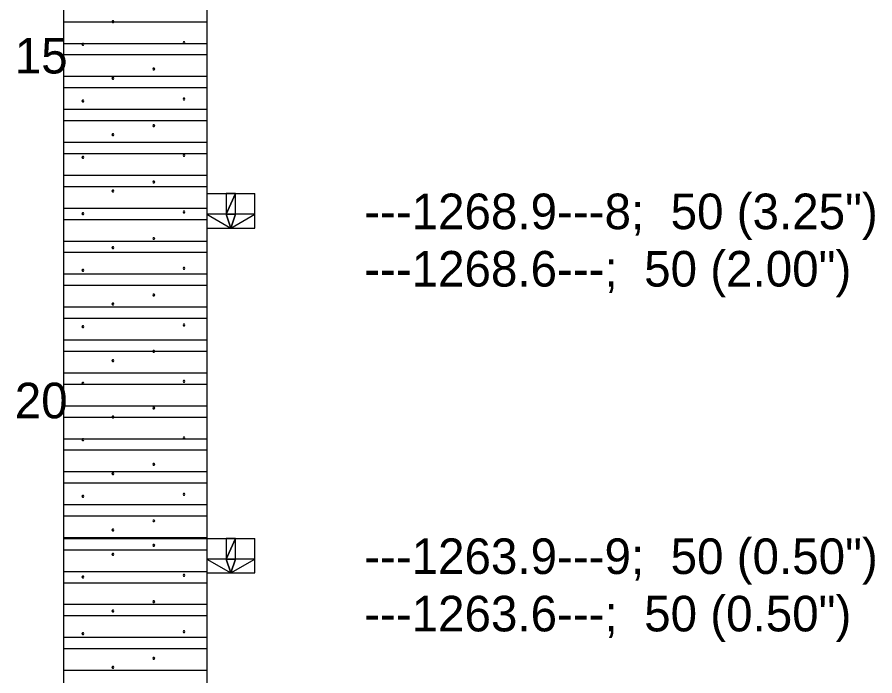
# Model space of a CAD drawing. Extents: x 2150148.6 to 2150220.1, y 143803.7 to 143875.1.
# Drawn here: x 2150191.798 to 2150194.79, y 143822.25 to 143824.546 of the extents above; entities that cross this region are included whole.
import ezdxf

# ---------------------------------------------------------------- set-up
doc = ezdxf.new("R2010")
doc.units = 0
doc.layers.add('Default', color=7, linetype='Continuous')

msp = doc.modelspace()

# ---------------------------------------------------------------- linework, layer by layer
at = {"layer": 'Default'}
for points in [[(2150191.9604, 143828.0174), (2150191.9604, 143817.9213)], [(2150192.4604, 143828.0174), (2150192.4604, 143817.9213)], [(2150191.9604, 143824.53), (2150192.4604, 143824.53)], [(2150192.1355, 143824.5299), (2150192.1338, 143824.5328), (2150192.1306, 143824.5328), (2150192.1289, 143824.53), (2150192.1306, 143824.5271), (2150192.1338, 143824.5271), (2150192.1355, 143824.5299)], [(2150192.3836, 143824.4575), (2150192.3819, 143824.4604), (2150192.3787, 143824.4604), (2150192.377, 143824.4575), (2150192.3787, 143824.4547), (2150192.3819, 143824.4547), (2150192.3836, 143824.4575)], [(2150191.9604, 143824.4545), (2150192.4604, 143824.4545)], [(2150192.0308, 143824.451), (2150192.0292, 143824.4538), (2150192.0259, 143824.4538), (2150192.0243, 143824.451), (2150192.0259, 143824.4481), (2150192.0292, 143824.4481), (2150192.0308, 143824.451)], [(2150191.9604, 143824.4152), (2150192.4604, 143824.4152)], [(2150192.2781, 143824.365), (2150192.2764, 143824.3678), (2150192.2731, 143824.3678), (2150192.2715, 143824.365), (2150192.2731, 143824.3622), (2150192.2764, 143824.3622), (2150192.2781, 143824.365)], [(2150191.9604, 143824.3397), (2150192.4604, 143824.3397)], [(2150192.1355, 143824.3331), (2150192.1338, 143824.336), (2150192.1306, 143824.336), (2150192.1289, 143824.3331), (2150192.1306, 143824.3303), (2150192.1338, 143824.3303), (2150192.1355, 143824.3331)], [(2150191.9604, 143824.3003), (2150192.4604, 143824.3003)], [(2150192.0308, 143824.2541), (2150192.0292, 143824.257), (2150192.0259, 143824.257), (2150192.0243, 143824.2541), (2150192.0259, 143824.2513), (2150192.0292, 143824.2513), (2150192.0308, 143824.2541)], [(2150192.3836, 143824.2606), (2150192.3819, 143824.2635), (2150192.3787, 143824.2635), (2150192.377, 143824.2606), (2150192.3787, 143824.2578), (2150192.3819, 143824.2578), (2150192.3836, 143824.2606)], [(2150191.9604, 143824.2249), (2150192.4604, 143824.2249)], [(2150191.9604, 143824.1855), (2150192.4604, 143824.1855)], [(2150192.2781, 143824.1681), (2150192.2764, 143824.1709), (2150192.2731, 143824.1709), (2150192.2715, 143824.1681), (2150192.2731, 143824.1653), (2150192.2764, 143824.1653), (2150192.2781, 143824.1681)], [(2150192.1355, 143824.1362), (2150192.1338, 143824.1391), (2150192.1306, 143824.1391), (2150192.1289, 143824.1363), (2150192.1306, 143824.1334), (2150192.1338, 143824.1334), (2150192.1355, 143824.1362)], [(2150191.9604, 143824.1101), (2150192.4604, 143824.1101)], [(2150191.9604, 143824.0707), (2150192.4604, 143824.0707)], [(2150192.0308, 143824.0573), (2150192.0292, 143824.0601), (2150192.0259, 143824.0601), (2150192.0243, 143824.0573), (2150192.0259, 143824.0544), (2150192.0292, 143824.0544), (2150192.0308, 143824.0573)], [(2150192.3836, 143824.0638), (2150192.3819, 143824.0667), (2150192.3787, 143824.0667), (2150192.377, 143824.0638), (2150192.3787, 143824.061), (2150192.3819, 143824.061), (2150192.3836, 143824.0638)], [(2150191.9604, 143823.9952), (2150192.4604, 143823.9952)], [(2150191.9604, 143823.9559), (2150192.4604, 143823.9559)], [(2150192.2781, 143823.9713), (2150192.2764, 143823.9741), (2150192.2731, 143823.9741), (2150192.2715, 143823.9713), (2150192.2731, 143823.9685), (2150192.2764, 143823.9685), (2150192.2781, 143823.9713)], [(2150192.1355, 143823.9394), (2150192.1338, 143823.9423), (2150192.1306, 143823.9423), (2150192.1289, 143823.9394), (2150192.1306, 143823.9366), (2150192.1338, 143823.9366), (2150192.1355, 143823.9394)], [(2150192.4604, 143823.9309), (2150192.6271, 143823.9309)], [(2150192.6271, 143823.8107), (2150192.6271, 143823.9309)], [(2150191.9604, 143823.8804), (2150192.4604, 143823.8804)], [(2150192.0308, 143823.8604), (2150192.0292, 143823.8633), (2150192.0259, 143823.8633), (2150192.0243, 143823.8604), (2150192.0259, 143823.8576), (2150192.0292, 143823.8576), (2150192.0308, 143823.8604)], [(2150192.3836, 143823.8669), (2150192.3819, 143823.8698), (2150192.3787, 143823.8698), (2150192.377, 143823.8669), (2150192.3787, 143823.8641), (2150192.3819, 143823.8641), (2150192.3836, 143823.8669)], [(2150191.9604, 143823.841), (2150192.4604, 143823.841)], [(2150192.4604, 143823.8107), (2150192.6271, 143823.8107)], [(2150192.2781, 143823.7744), (2150192.2764, 143823.7772), (2150192.2731, 143823.7772), (2150192.2715, 143823.7744), (2150192.2731, 143823.7716), (2150192.2764, 143823.7716), (2150192.2781, 143823.7744)], [(2150191.9604, 143823.7656), (2150192.4604, 143823.7656)], [(2150192.1355, 143823.7425), (2150192.1338, 143823.7454), (2150192.1306, 143823.7454), (2150192.1289, 143823.7426), (2150192.1306, 143823.7397), (2150192.1338, 143823.7397), (2150192.1355, 143823.7425)], [(2150191.9604, 143823.7262), (2150192.4604, 143823.7262)], [(2150191.9604, 143823.6507), (2150192.4604, 143823.6507)], [(2150192.0308, 143823.6636), (2150192.0292, 143823.6664), (2150192.0259, 143823.6664), (2150192.0243, 143823.6636), (2150192.0259, 143823.6607), (2150192.0292, 143823.6607), (2150192.0308, 143823.6636)], [(2150192.3836, 143823.6701), (2150192.3819, 143823.673), (2150192.3787, 143823.673), (2150192.377, 143823.6701), (2150192.3787, 143823.6673), (2150192.3819, 143823.6673), (2150192.3836, 143823.6701)], [(2150191.9604, 143823.6114), (2150192.4604, 143823.6114)], [(2150192.2781, 143823.5776), (2150192.2764, 143823.5804), (2150192.2731, 143823.5804), (2150192.2715, 143823.5776), (2150192.2731, 143823.5748), (2150192.2764, 143823.5748), (2150192.2781, 143823.5776)], [(2150191.9604, 143823.5359), (2150192.4604, 143823.5359)], [(2150192.1355, 143823.5457), (2150192.1338, 143823.5486), (2150192.1306, 143823.5486), (2150192.1289, 143823.5457), (2150192.1306, 143823.5429), (2150192.1338, 143823.5429), (2150192.1355, 143823.5457)], [(2150191.9604, 143823.4965), (2150192.4604, 143823.4965)], [(2150192.0308, 143823.4667), (2150192.0292, 143823.4696), (2150192.0259, 143823.4696), (2150192.0243, 143823.4667), (2150192.0259, 143823.4639), (2150192.0292, 143823.4639), (2150192.0308, 143823.4667)], [(2150192.3836, 143823.4732), (2150192.3819, 143823.4761), (2150192.3787, 143823.4761), (2150192.377, 143823.4732), (2150192.3787, 143823.4704), (2150192.3819, 143823.4704), (2150192.3836, 143823.4732)], [(2150191.9604, 143823.4211), (2150192.4604, 143823.4211)], [(2150191.9604, 143823.3817), (2150192.4604, 143823.3817)], [(2150192.2781, 143823.3807), (2150192.2764, 143823.3835), (2150192.2731, 143823.3835), (2150192.2715, 143823.3807), (2150192.2731, 143823.3779), (2150192.2764, 143823.3779), (2150192.2781, 143823.3807)], [(2150192.1355, 143823.3488), (2150192.1338, 143823.3517), (2150192.1306, 143823.3517), (2150192.1289, 143823.3489), (2150192.1306, 143823.346), (2150192.1338, 143823.346), (2150192.1355, 143823.3488)], [(2150191.9604, 143823.3062), (2150192.4604, 143823.3062)], [(2150191.9604, 143823.2669), (2150192.4604, 143823.2669)], [(2150192.0308, 143823.2699), (2150192.0292, 143823.2727), (2150192.0259, 143823.2727), (2150192.0243, 143823.2699), (2150192.0259, 143823.267), (2150192.0292, 143823.267), (2150192.0308, 143823.2699)], [(2150192.3836, 143823.2764), (2150192.3819, 143823.2793), (2150192.3787, 143823.2793), (2150192.377, 143823.2764), (2150192.3787, 143823.2736), (2150192.3819, 143823.2736), (2150192.3836, 143823.2764)], [(2150191.9604, 143823.1914), (2150192.4604, 143823.1914)], [(2150192.2781, 143823.1839), (2150192.2764, 143823.1867), (2150192.2731, 143823.1867), (2150192.2715, 143823.1839), (2150192.2731, 143823.1811), (2150192.2764, 143823.1811), (2150192.2781, 143823.1839)], [(2150191.9604, 143823.152), (2150192.4604, 143823.152)], [(2150192.1355, 143823.152), (2150192.1338, 143823.1549), (2150192.1306, 143823.1549), (2150192.1289, 143823.152), (2150192.1306, 143823.1492), (2150192.1338, 143823.1492), (2150192.1355, 143823.152)], [(2150192.3836, 143823.0795), (2150192.3819, 143823.0824), (2150192.3787, 143823.0824), (2150192.377, 143823.0795), (2150192.3787, 143823.0767), (2150192.3819, 143823.0767), (2150192.3836, 143823.0795)], [(2150191.9604, 143823.0766), (2150192.4604, 143823.0766)], [(2150192.0308, 143823.073), (2150192.0292, 143823.0759), (2150192.0259, 143823.0759), (2150192.0243, 143823.073), (2150192.0259, 143823.0702), (2150192.0292, 143823.0702), (2150192.0308, 143823.073)], [(2150191.9604, 143823.0372), (2150192.4604, 143823.0372)], [(2150191.9604, 143822.9618), (2150192.4604, 143822.9618)], [(2150192.2781, 143822.987), (2150192.2764, 143822.9898), (2150192.2731, 143822.9898), (2150192.2715, 143822.987), (2150192.2731, 143822.9842), (2150192.2764, 143822.9842), (2150192.2781, 143822.987)], [(2150192.1355, 143822.9551), (2150192.1338, 143822.958), (2150192.1306, 143822.958), (2150192.1289, 143822.9552), (2150192.1306, 143822.9523), (2150192.1338, 143822.9523), (2150192.1355, 143822.9551)], [(2150191.9604, 143822.9224), (2150192.4604, 143822.9224)], [(2150192.0308, 143822.8762), (2150192.0292, 143822.879), (2150192.0259, 143822.879), (2150192.0243, 143822.8762), (2150192.0259, 143822.8733), (2150192.0292, 143822.8733), (2150192.0308, 143822.8762)], [(2150192.3836, 143822.8827), (2150192.3819, 143822.8856), (2150192.3787, 143822.8856), (2150192.377, 143822.8827), (2150192.3787, 143822.8799), (2150192.3819, 143822.8799), (2150192.3836, 143822.8827)], [(2150191.9604, 143822.8469), (2150192.4604, 143822.8469)], [(2150191.9604, 143822.8076), (2150192.4604, 143822.8076)], [(2150192.2781, 143822.7902), (2150192.2764, 143822.793), (2150192.2731, 143822.793), (2150192.2715, 143822.7902), (2150192.2731, 143822.7874), (2150192.2764, 143822.7874), (2150192.2781, 143822.7902)], [(2150192.1355, 143822.7583), (2150192.1338, 143822.7612), (2150192.1306, 143822.7612), (2150192.1289, 143822.7583), (2150192.1306, 143822.7555), (2150192.1338, 143822.7555), (2150192.1355, 143822.7583)], [(2150191.9604, 143822.7321), (2150192.4604, 143822.7321)], [(2150191.9604, 143822.7289), (2150192.4604, 143822.7289)], [(2150191.9604, 143822.7289), (2150192.4604, 143822.7289)], [(2150192.4604, 143822.7289), (2150192.6271, 143822.7289)], [(2150192.6271, 143822.6088), (2150192.6271, 143822.7289)], [(2150192.2781, 143822.705), (2150192.2764, 143822.7078), (2150192.2731, 143822.7078), (2150192.2715, 143822.705), (2150192.2731, 143822.7022), (2150192.2764, 143822.7022), (2150192.2781, 143822.705)], [(2150191.9604, 143822.6896), (2150192.4604, 143822.6896)], [(2150192.1355, 143822.6731), (2150192.1338, 143822.676), (2150192.1306, 143822.676), (2150192.1289, 143822.6732), (2150192.1306, 143822.6703), (2150192.1338, 143822.6703), (2150192.1355, 143822.6731)], [(2150191.9604, 143822.6141), (2150192.4604, 143822.6141)], [(2150192.3836, 143822.6007), (2150192.3819, 143822.6036), (2150192.3787, 143822.6036), (2150192.377, 143822.6007), (2150192.3787, 143822.5978), (2150192.3819, 143822.5978), (2150192.3836, 143822.6007)], [(2150192.4604, 143822.6088), (2150192.6271, 143822.6088)], [(2150191.9604, 143822.5747), (2150192.4604, 143822.5747)], [(2150192.0308, 143822.5942), (2150192.0292, 143822.597), (2150192.0259, 143822.597), (2150192.0243, 143822.5942), (2150192.0259, 143822.5913), (2150192.0292, 143822.5913), (2150192.0308, 143822.5942)], [(2150191.9604, 143822.4993), (2150192.4604, 143822.4993)], [(2150192.2781, 143822.5081), (2150192.2764, 143822.511), (2150192.2731, 143822.511), (2150192.2715, 143822.5081), (2150192.2731, 143822.5053), (2150192.2764, 143822.5053), (2150192.2781, 143822.5081)], [(2150191.9604, 143822.4599), (2150192.4604, 143822.4599)], [(2150192.1355, 143822.4763), (2150192.1338, 143822.4791), (2150192.1306, 143822.4791), (2150192.1289, 143822.4763), (2150192.1306, 143822.4734), (2150192.1338, 143822.4734), (2150192.1355, 143822.4763)], [(2150192.0308, 143822.3973), (2150192.0292, 143822.4001), (2150192.0259, 143822.4001), (2150192.0243, 143822.3973), (2150192.0259, 143822.3944), (2150192.0292, 143822.3944), (2150192.0308, 143822.3973)], [(2150192.3836, 143822.4038), (2150192.3819, 143822.4067), (2150192.3787, 143822.4067), (2150192.377, 143822.4038), (2150192.3787, 143822.401), (2150192.3819, 143822.401), (2150192.3836, 143822.4038)], [(2150191.9604, 143822.3845), (2150192.4604, 143822.3845)], [(2150191.9604, 143822.3451), (2150192.4604, 143822.3451)], [(2150192.2781, 143822.3113), (2150192.2764, 143822.3141), (2150192.2731, 143822.3141), (2150192.2715, 143822.3113), (2150192.2731, 143822.3085), (2150192.2764, 143822.3085), (2150192.2781, 143822.3113)], [(2150192.1355, 143822.2794), (2150192.1338, 143822.2823), (2150192.1306, 143822.2823), (2150192.1289, 143822.2795), (2150192.1306, 143822.2766), (2150192.1338, 143822.2766), (2150192.1355, 143822.2794)], [(2150191.9604, 143822.2696), (2150192.4604, 143822.2696)]]:
    msp.add_lwpolyline(points, dxfattribs=at)
for points in [[(2150192.5271, 143823.8588), (2150192.5604, 143823.8588), (2150192.5604, 143823.9309), (2150192.5271, 143823.8588)], [(2150192.5271, 143823.8588), (2150192.5604, 143823.9309), (2150192.5271, 143823.9309), (2150192.5271, 143823.8588)], [(2150192.5271, 143823.8588), (2150192.4604, 143823.8588), (2150192.5437, 143823.8107), (2150192.5271, 143823.8588)], [(2150192.5271, 143823.8588), (2150192.5437, 143823.8107), (2150192.5604, 143823.8588), (2150192.5271, 143823.8588)], [(2150192.5437, 143823.8107), (2150192.6271, 143823.8588), (2150192.5604, 143823.8588), (2150192.5437, 143823.8107)], [(2150192.5271, 143822.6568), (2150192.5604, 143822.6568), (2150192.5604, 143822.7289), (2150192.5271, 143822.6568)], [(2150192.5271, 143822.6568), (2150192.5604, 143822.7289), (2150192.5271, 143822.7289), (2150192.5271, 143822.6568)], [(2150192.5271, 143822.6568), (2150192.4604, 143822.6568), (2150192.5437, 143822.6088), (2150192.5271, 143822.6568)], [(2150192.5271, 143822.6568), (2150192.5437, 143822.6088), (2150192.5604, 143822.6568), (2150192.5271, 143822.6568)], [(2150192.5437, 143822.6088), (2150192.6271, 143822.6568), (2150192.5604, 143822.6568), (2150192.5437, 143822.6088)]]:
    msp.add_lwpolyline(points, close=True, dxfattribs=at)

# ---------------------------------------------------------------- texts
for s, p in [('15', (2150191.79, 143824.3496)), ('---1268.9---8;  50 (3.25")', (2150193.0084, 143823.8069)), ('---1268.6---;  50 (2.00")', (2150193.0084, 143823.6069)), ('20', (2150191.79, 143823.1477)), ('---1263.9---9;  50 (0.50")', (2150193.0084, 143822.6049)), ('---1263.6---;  50 (0.50")', (2150193.0084, 143822.4049))]:
    msp.add_text(s, height=0.124, dxfattribs=at).set_placement(p)

doc.saveas('drawing.dxf')
